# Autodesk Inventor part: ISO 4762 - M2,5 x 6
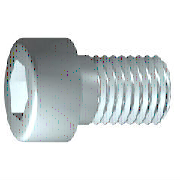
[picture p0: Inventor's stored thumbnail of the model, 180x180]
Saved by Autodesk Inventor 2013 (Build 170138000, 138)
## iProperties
Created: 2012-02
Part Number: ISO 4762 - M2,5 x 6
Material: Stainless Steel, 440C
Description: Hexagon Socket Head Cap Screw
Document SubType Name: Modeling
Standard: ISO 4762
Designer: rYan
Standard Revision: Fourth edition 2004-03-01
Standards Organization: ISO
Language: en-US
Size Designation: M2,5 x 6
Categories: <MemberInstance><Categories><Category DisplayName="Fasteners" InternalName="e4da775c-781d-43d5-af7c-5136215cf5a6" Mnemonic="FSTN"><Category DisplayName="Bolts"
Density: 7.75 g/cm^3
IsCustomPart: 0
Author: rYan
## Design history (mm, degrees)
sketch "Sketch1"
  geometry: L1 (-0.733, 0)-(6, 0); L2 (6, 0)-(6, 1.25); L3 (6, 1.25)-(1.125, 1.25); L4 (1.125, 1.25)-(0.849, 1.25); L5 (0.849, 1.25)-(0, 1.25); L6 (0, 1.25)-(0, 2.25); L7 (0, 2.25)-(-2.5, 2.25); L8 (-2.5, 2.25)-(-2.5, 1.155); L9 (-2.5, 1.155)-(-1.4, 1.155); L10 (-1.4, 1.155)-(-0.733, 0); L11 (-4.2, 0)-(7.7, 0) reference; L12 (0, -0.45)-(0, 2.7) reference; L13 (1.125, 1.25)-(0, 1.25)
  constraints: 22 end point, 6 parallel, 2 collinear, 2 perpendicular, 1 horizontal, 1 point on line
  dimensions: "d1" = 4.875 distance from line of L3.end L2 (= GEL); "d2" = 0.27615 distance of L4.end L3.end (computed from GAL); "d3" = 2.5 distance between parallel lines of L8 L6 (= KOH); "d4" = 1.1 distance of L8.end L9.end (= INTI); "d5" = 60 deg angle of L10 L1; "d6" = 2.5 diameter of L3 L1 (= GD); "d7" = 2.5 diameter of L5 L1 (= BDM); "d8" = 2.3094 diameter of L9 L1 (= 1.1547 x SW); "d9" = 4.5 diameter of L7 L1 (= KOD); "d26" = 6 distance between parallel lines of L12 L2 (= NLG)
revolve "Body" sketch "Sketch1" stored, may be unused: angle "d10" = 90 deg
sketch "Sketch2"
  geometry: L1 (0, -3.15)-(0, 3.15) reference; L2 (-3.15, 0)-(3.15, 0) reference; L3 (1.155, 0)-(0.577, -1); L4 (0.577, -1)-(-0.577, -1); L5 (-0.577, -1)-(-1.155, 0); L6 (-1.155, 0)-(-0.577, 1); L7 (-0.577, 1)-(0.577, 1); L8 (0.577, 1)-(1.155, 0); 2 further points
  constraints: 12 end point, 1 coincident, 1 horizontal alignment, 1 point on line, 12 other
extrude "Slot" join sketch "Sketch2" stored distance "d11" = 10; taper "d12" = 0 deg
workplane "Work Plane1"
fillet "Fillet2" dims "d30" = 0.1 (= R)
body "Solid1"
fillet "Fillet1" dims "d17" = 0.25 (= RR)
feature "Thread" dims "d13" = 4.875 (= GEL), "d14" = 0
chamfer "Chamfer1" distance "d15" = 0.27605 (= -0.5 x SPD + 0.5 x GD); stored, may be unused: second distance "d16" = 0.27605 (= GUL), angle "d27" = 45 deg
other parameters: "GD" = 2.5 [user parameter; used in 2 equation terms], "NLG" = 6 [user parameter; used in 1 equation term], "GEL" = 4.875 [user parameter; used in 2 equation terms], "KOD" = 4.5 [user parameter; used in 1 equation term], "KOH" = 2.5 [user parameter; used in 1 equation term], "INTI" = 1.1 [user parameter; used in 1 equation term], "GAL" = 0.27605 (= 0.61345 x PTC) [user parameter; used in 1 equation term], "GUL" = 0.27605 (= 0.61345 x PTC) [user parameter; used in 1 equation term], "BDM" = 2.5 (= NND) [user parameter; used in 1 equation term], "SW" = 2 [user parameter; used in 2 equation terms], "RR" = 0.25 [user parameter; used in 1 equation term], "SPD" = 1.94789 (= NND - 1.2269 x PTC) [user parameter; used in 1 equation term], "d19" = 0, "d28" = 0, "d29" = 0, "R" = 0.1 [user parameter; used in 1 equation term], "TOA" = 30 deg [user parameter], "GD1" = 1.94789 (= THREADDIA - 1.2269 x PTC) [user parameter], "THREADDIA" = 2.5 [user parameter; used in 1 equation term], "FAWI" = 45 deg [user parameter], "TPU" = 22.22222 (computed from PTC) [user parameter], "PTC" = 0.45 [user parameter; used in 5 equation terms], "NND" = 2.5 [user parameter; used in 2 equation terms], "E0" = 2.31 (= 1.155 x SW) [user parameter]
